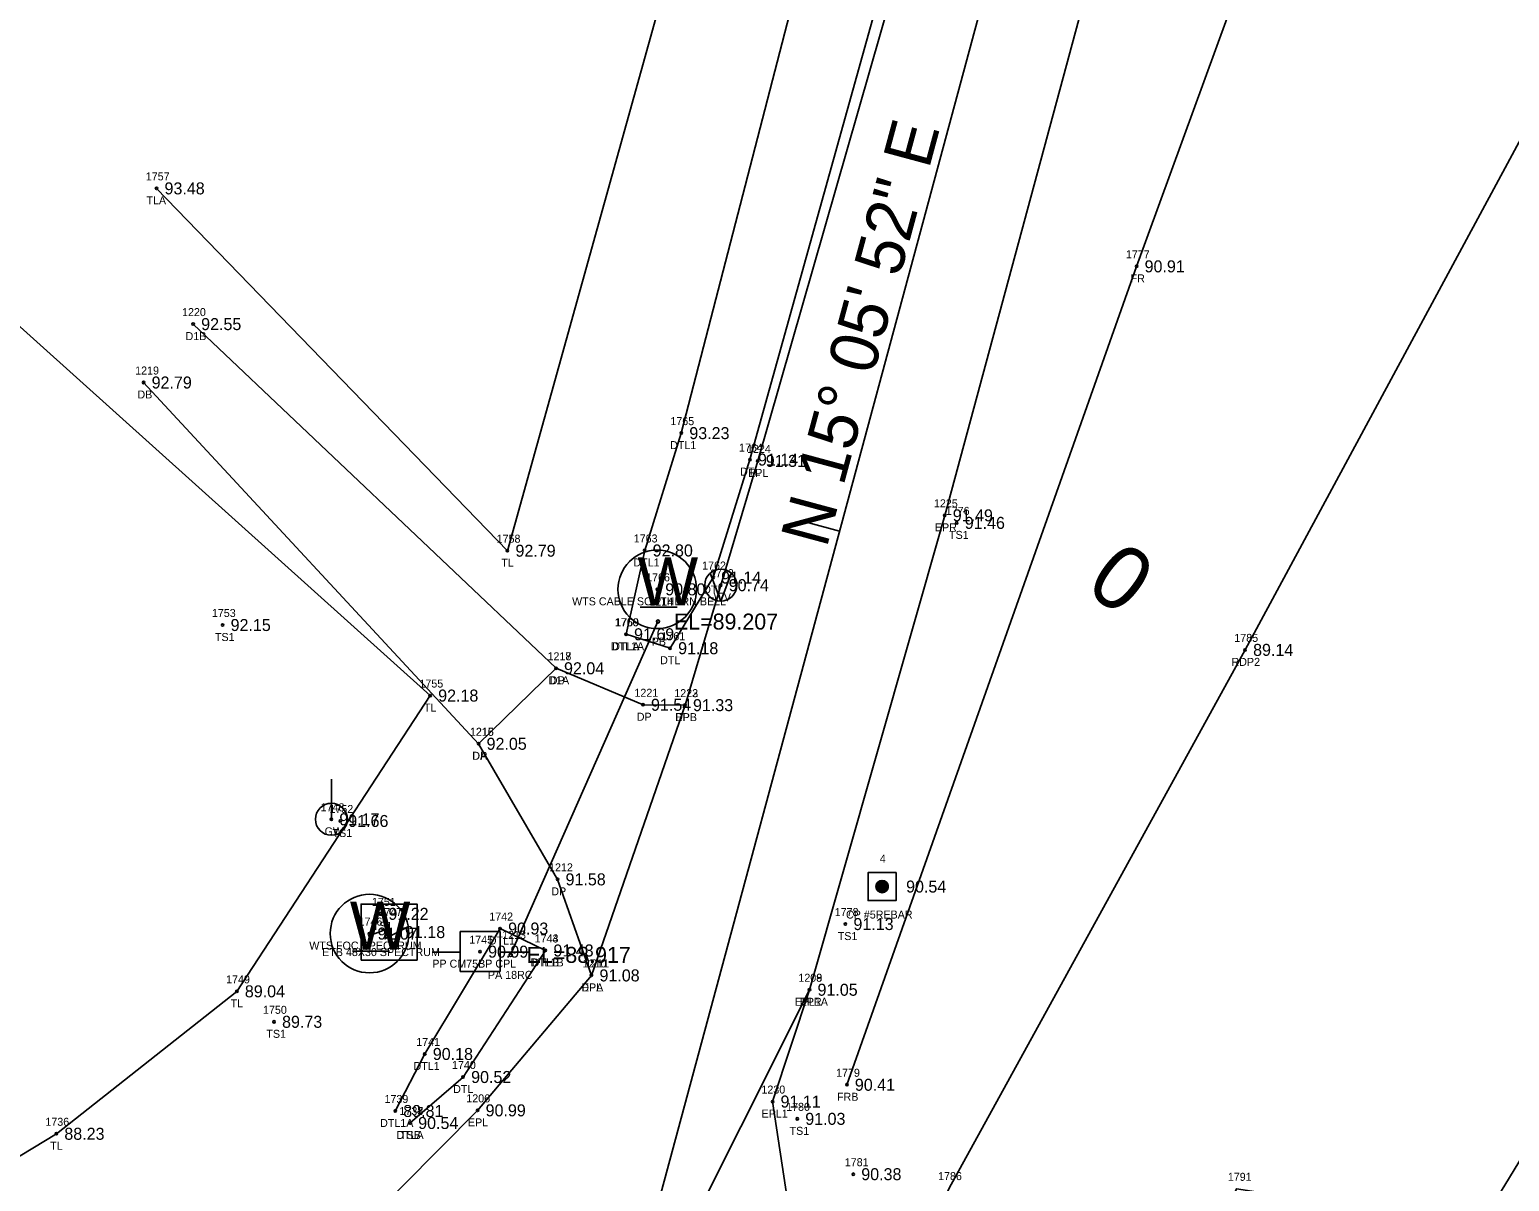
# Model space of a CAD drawing. Extents: x 2529517 to 2532038, y 935000 to 936944.
# Drawn here: x 2531691.2 to 2531876.1, y 936351.6 to 936495.6 of the extents above; entities that cross this region are included whole.
import ezdxf

# ---------------------------------------------------------------- set-up
doc = ezdxf.new("R2010")
doc.units = 0
for name, color, linetype in [('Default', 7, 'Continuous'), ('RD_DTM_BkLn_txCode', 7, 'Continuous'), ('RD_EX_DR_ErosCtrl', 7, 'Continuous'), ('RD_EX_DR_ErosCtrl_txCode', 7, 'Continuous'), ('RD_EX_DR_Pipe', 7, 'Continuous'), ('RD_EX_DR_Pipe_txCode', 7, 'Continuous'), ('RD_EX_Driveway', 7, 'Continuous'), ('RD_EX_Driveway_txCode', 7, 'Continuous'), ('RD_EX_Fence_Other', 7, 'Continuous'), ('RD_EX_Fence_Other_txCode', 7, 'Continuous'), ('RD_EX_H2O', 7, 'Continuous'), ('RD_EX_H2O_txCode', 7, 'Continuous'), ('RD_EX_Road', 7, 'Continuous'), ('RD_EX_Road_txCode', 7, 'Continuous'), ('RD_EX_TX_DR_ErosCtrl_ELEV', 7, 'Continuous'), ('RD_EX_TX_Driveway_ELEV', 7, 'Continuous'), ('RD_EX_TX_Fence_Other_ELEV', 7, 'Continuous'), ('RD_EX_TX_H2O_ELEV', 7, 'Continuous'), ('RD_EX_TX_Misc_ELEV', 7, 'Continuous'), ('RD_EX_TX_Road_ELEV', 7, 'Continuous'), ('RD_EX_TX_UT_ELEV', 7, 'Continuous'), ('RD_EX_TX_VEG_ELEV', 7, 'Continuous'), ('RD_EX_UT', 7, 'Continuous'), ('RD_EX_UT_txCode', 7, 'Continuous'), ('RD_EX_VEG', 7, 'Continuous'), ('RD_EX_VEG_txCode', 7, 'Continuous'), ('RD_HC_Cl', 7, 'Continuous'), ('RD_HC_Data', 7, 'Continuous'), ('RD_HC_Data_Tic', 7, 'Continuous'), ('RD_HC_Survey', 7, 'Continuous'), ('RD_HC_Survey_ELEV', 7, 'Continuous'), ('RD_HC_Survey_txCode', 7, 'Continuous'), ('RD_HC_TX_Sta50', 7, 'Continuous'), ('RD_SMD_Locator', 7, 'Continuous'), ('RD_TX_Pipe_ElevEX', 7, 'Continuous')]:
    doc.layers.add(name, color=color, linetype=linetype)

msp = doc.modelspace()

# ---------------------------------------------------------------- linework, layer by layer
at = {"layer": 'Default'}
msp.add_line((2531768.07, 936342.55), (2531830.33, 936573.34), dxfattribs=at)
at = {"layer": 'RD_EX_DR_ErosCtrl'}
for points in [[(2531913.23, 936552.65), (2531879.89, 936486.26), (2531843.11, 936418.02), (2531806.11, 936350.73), (2531797.19, 936330.95), (2531817.13, 936316.37), (2531822.13, 936313.28)], [(2531826.03, 936317.37), (2531842.02, 936350.64), (2531872.46, 936345.98), (2531906.05, 936401.13), (2531944.32, 936458.1), (2531968.34, 936447.83), (2531976.81, 936458.99), (2531957.81, 936476.14), (2531966.51, 936493.14)]]:
    msp.add_lwpolyline(points, dxfattribs=at)
at = {"layer": 'RD_EX_DR_Pipe'}
msp.add_line((2531751.32, 936379.89), (2531769.73, 936421.56), dxfattribs=at)
at = {"layer": 'RD_EX_Driveway'}
for p, q in [((2531756.99, 936415.72), (2531711.64, 936458.75)), ((2531747.31, 936406.28), (2531705.45, 936451.45))]:
    msp.add_line(p, q, dxfattribs=at)
msp.add_lwpolyline([(2531761.42, 936377.32), (2531757.18, 936389.33), (2531747.31, 936406.28), (2531756.99, 936415.72), (2531767.86, 936411.16), (2531773.11, 936411.11)], dxfattribs=at)
at = {"layer": 'RD_EX_Fence_Other'}
msp.add_lwpolyline([(2531868.07, 936571.73), (2531829.55, 936465.97), (2531793.34, 936363.65)], dxfattribs=at)
at = {"layer": 'RD_EX_H2O'}
for points in [[(2531765.74, 936419.97), (2531768.07, 936430.45), (2531772.65, 936445.12), (2531791.42, 936517.8), (2531810.23, 936589.19)], [(2531765.74, 936419.97), (2531771.25, 936418.23), (2531776.62, 936427.07), (2531781.23, 936441.81), (2531801.62, 936515.08), (2531818.73, 936586.25)], [(2531736.9, 936360.37), (2531740.59, 936367.5), (2531750, 936383.18), (2531755.67, 936380.44)], [(2531738.76, 936358.87), (2531745.38, 936364.62), (2531755.67, 936380.44)]]:
    msp.add_lwpolyline(points, dxfattribs=at)
at = {"layer": 'RD_EX_Road'}
for points in [[(2531169.65, 936000.77), (2531208.79, 936024.95), (2531292.04, 936074.02), (2531376.24, 936123.7), (2531460.37, 936174.49), (2531542.92, 936223.44), (2531626.67, 936270.85), (2531672.4, 936298.39), (2531714.28, 936327.21), (2531747.19, 936360.45), (2531761.42, 936377.32), (2531773.11, 936411.11), (2531782.2, 936441.65), (2531803.17, 936514.76), (2531820.28, 936585.8)], [(2531180.82, 935982), (2531220.82, 936004.21), (2531303.54, 936053.39), (2531388.75, 936103.71), (2531472.27, 936152.98), (2531554.79, 936201.9), (2531638.11, 936250.92), (2531683.19, 936278.28), (2531730.37, 936304.55), (2531771.5, 936341.26), (2531788.67, 936375.53), (2531805.57, 936434.84), (2531825.53, 936508.74), (2531844.13, 936579.65)], [(2531788.67, 936375.53), (2531784.05, 936361.55), (2531786.68, 936344.28), (2531790.66, 936334.1), (2531795.41, 936327.11), (2531801.08, 936320.84), (2531849.6, 936283.17), (2531876.01, 936264.22), (2531894.71, 936249.13), (2531930.69, 936221.59), (2532010.91, 936160.51)]]:
    msp.add_lwpolyline(points, dxfattribs=at)
at = {"layer": 'RD_EX_UT'}
for p, q in [((2531777.57, 936424.11), (2531776.26, 936427.6)), ((2531777.57, 936424.11), (2531778.89, 936427.56)), ((2531767.51, 936423.38), (2531772.14, 936423.38)), ((2531728.91, 936396.84), (2531728.91, 936401.84)), ((2531749.99, 936382.8), (2531744.99, 936382.8)), ((2531744.99, 936382.8), (2531744.99, 936377.8)), ((2531749.99, 936377.8), (2531749.99, 936382.8)), ((2531731.55, 936380.34), (2531736.18, 936380.34)), ((2531741.56, 936380.24), (2531745.03, 936380.24)), ((2531749.92, 936380.24), (2531753.56, 936380.24)), ((2531744.99, 936377.8), (2531749.99, 936377.8))]:
    msp.add_line(p, q, dxfattribs=at)
msp.add_lwpolyline([(2531732.62, 936379.24), (2531732.62, 936386.24), (2531739.62, 936386.24), (2531739.62, 936379.24)], close=True, dxfattribs=at)
msp.add_lwpolyline([(2531733.52, 936382.23), (2531735.94, 936383.14), (2531735.6, 936381.89), (2531738.64, 936383.48)], dxfattribs=at)
for centre, radius in [((2531769.64, 936425.59), 4.91), ((2531777.57, 936426.11), 2), ((2531728.91, 936396.84), 2), ((2531733.68, 936382.55), 4.91)]:
    msp.add_circle(centre, radius, dxfattribs=at)
at = {"layer": 'RD_EX_VEG'}
for points in [[(2531707.06, 936475.72), (2531750.92, 936430.42), (2531796.48, 936594.01)], [(2531179.62, 936140.26), (2531216.45, 936067.89), (2531694.54, 936357.52), (2531717.1, 936375.33), (2531741.26, 936412.31), (2531677.61, 936469.53)]]:
    msp.add_lwpolyline(points, dxfattribs=at)
at = {"layer": 'RD_HC_Cl'}
msp.add_line((2531768.07, 936342.55), (2531830.33, 936573.34), dxfattribs=at)
at = {"layer": 'RD_HC_Data_Tic'}
msp.add_line((2531792.43, 936432.85), (2531788.57, 936433.89), dxfattribs=at)
at = {"layer": 'RD_HC_Survey'}
for p, q in [((2531796.99, 936388.25), (2531796.99, 936388.61)), ((2531797.02, 936388.17), (2531797.02, 936388.69)), ((2531797.04, 936388.11), (2531797.04, 936388.76)), ((2531797.06, 936388.06), (2531797.06, 936388.8)), ((2531797.09, 936388.02), (2531797.09, 936388.85)), ((2531797.11, 936387.98), (2531797.11, 936388.88)), ((2531797.14, 936387.95), (2531797.14, 936388.92)), ((2531797.16, 936387.92), (2531797.16, 936388.94)), ((2531797.19, 936387.9), (2531797.19, 936388.97)), ((2531797.21, 936387.87), (2531797.21, 936389)), ((2531797.24, 936387.85), (2531797.24, 936389.02)), ((2531797.26, 936387.83), (2531797.26, 936389.04)), ((2531797.29, 936387.81), (2531797.29, 936389.06)), ((2531797.31, 936387.79), (2531797.31, 936389.07)), ((2531797.34, 936387.78), (2531797.34, 936389.09)), ((2531797.36, 936387.76), (2531797.36, 936389.1)), ((2531797.39, 936387.75), (2531797.39, 936389.12)), ((2531797.41, 936387.74), (2531797.41, 936389.13)), ((2531797.44, 936387.73), (2531797.44, 936389.14)), ((2531797.46, 936387.72), (2531797.46, 936389.15)), ((2531797.49, 936387.71), (2531797.49, 936389.16)), ((2531797.51, 936387.7), (2531797.51, 936389.17)), ((2531797.53, 936387.69), (2531797.53, 936389.18)), ((2531797.56, 936387.68), (2531797.56, 936389.18)), ((2531797.58, 936387.68), (2531797.58, 936389.19)), ((2531797.61, 936387.67), (2531797.61, 936389.19)), ((2531797.63, 936387.67), (2531797.63, 936389.2)), ((2531797.66, 936387.67), (2531797.66, 936389.2)), ((2531797.68, 936387.67), (2531797.68, 936389.2)), ((2531797.71, 936387.66), (2531797.71, 936389.2)), ((2531797.73, 936387.66), (2531797.73, 936389.2)), ((2531797.76, 936387.66), (2531797.76, 936389.2)), ((2531797.78, 936387.66), (2531797.78, 936389.2)), ((2531797.81, 936387.67), (2531797.81, 936389.2)), ((2531797.83, 936387.67), (2531797.83, 936389.2)), ((2531797.86, 936387.67), (2531797.86, 936389.19)), ((2531797.88, 936387.68), (2531797.88, 936389.19)), ((2531797.91, 936387.68), (2531797.91, 936389.18)), ((2531797.93, 936387.69), (2531797.93, 936389.18)), ((2531797.96, 936387.69), (2531797.96, 936389.17)), ((2531797.98, 936387.7), (2531797.98, 936389.16)), ((2531798.01, 936387.71), (2531798.01, 936389.16)), ((2531798.03, 936387.72), (2531798.03, 936389.15)), ((2531798.05, 936387.73), (2531798.05, 936389.13)), ((2531798.08, 936387.74), (2531798.08, 936389.12)), ((2531798.1, 936387.76), (2531798.1, 936389.11)), ((2531798.13, 936387.77), (2531798.13, 936389.1)), ((2531798.15, 936387.79), (2531798.15, 936389.08)), ((2531798.18, 936387.8), (2531798.18, 936389.06)), ((2531798.2, 936387.82), (2531798.2, 936389.05)), ((2531798.23, 936387.84), (2531798.23, 936389.03)), ((2531798.25, 936387.86), (2531798.25, 936389.01)), ((2531798.28, 936387.88), (2531798.28, 936388.98)), ((2531798.3, 936387.91), (2531798.3, 936388.96)), ((2531798.33, 936387.94), (2531798.33, 936388.93)), ((2531798.35, 936387.97), (2531798.35, 936388.9)), ((2531798.38, 936388), (2531798.38, 936388.86)), ((2531798.4, 936388.04), (2531798.4, 936388.82)), ((2531798.43, 936388.09), (2531798.43, 936388.78)), ((2531798.45, 936388.14), (2531798.45, 936388.73)), ((2531798.48, 936388.21), (2531798.48, 936388.66)), ((2531798.5, 936388.32), (2531798.5, 936388.54))]:
    msp.add_line(p, q, dxfattribs=at)
msp.add_lwpolyline([(2531799.49, 936390.18), (2531795.99, 936390.18), (2531795.99, 936386.68), (2531799.49, 936386.68)], close=True, dxfattribs=at)
msp.add_circle((2531797.74, 936388.43), 0.769, dxfattribs=at)
at = {"layer": 'RD_SMD_Locator'}
for centre, radius in [((2531707.06, 936475.72), 0.15), ((2531829.55, 936465.97), 0.15), ((2531711.64, 936458.75), 0.15), ((2531705.45, 936451.45), 0.15), ((2531772.65, 936445.12), 0.15), ((2531781.23, 936441.81), 0.15), ((2531782.2, 936441.65), 0.15), ((2531805.57, 936434.84), 0.15), ((2531807.07, 936433.9), 0.15), ((2531750.92, 936430.42), 0.15), ((2531768.07, 936430.45), 0.15), ((2531769.64, 936425.59), 0.15), ((2531776.62, 936427.07), 0.15), ((2531777.57, 936426.11), 0.15), ((2531715.32, 936421.13), 0.15), ((2531765.74, 936419.97), 0.15), ((2531765.74, 936419.97), 0.15), ((2531769.73, 936421.56), 0.2), ((2531771.25, 936418.23), 0.15), ((2531843.11, 936418.02), 0.15), ((2531756.99, 936415.72), 0.15), ((2531756.99, 936415.72), 0.15), ((2531741.26, 936412.31), 0.15), ((2531767.86, 936411.16), 0.15), ((2531773.11, 936411.11), 0.15), ((2531773.11, 936411.11), 0.15), ((2531747.31, 936406.28), 0.15), ((2531747.31, 936406.28), 0.15), ((2531728.91, 936396.84), 0.15), ((2531730.02, 936396.63), 0.15), ((2531757.18, 936389.33), 0.15), ((2531797.74, 936388.43), 0.15), ((2531735.04, 936385.02), 0.15), ((2531750, 936383.18), 0.15), ((2531793.16, 936383.74), 0.15), ((2531733.68, 936382.55), 0.15), ((2531736.12, 936382.74), 0.15), ((2531747.5, 936380.29), 0.15), ((2531751.32, 936379.89), 0.2), ((2531755.67, 936380.44), 0.15), ((2531755.67, 936380.44), 0.15), ((2531761.42, 936377.32), 0.15), ((2531761.42, 936377.32), 0.15), ((2531788.67, 936375.53), 0.15), ((2531788.67, 936375.53), 0.15), ((2531717.1, 936375.33), 0.15), ((2531721.75, 936371.52), 0.15), ((2531740.59, 936367.5), 0.15), ((2531745.38, 936364.62), 0.15), ((2531793.34, 936363.65), 0.15), ((2531784.05, 936361.55), 0.15), ((2531736.9, 936360.37), 0.15), ((2531738.76, 936358.87), 0.15), ((2531738.76, 936358.87), 0.15), ((2531747.19, 936360.45), 0.15), ((2531787.14, 936359.39), 0.15), ((2531694.54, 936357.52), 0.15), ((2531794.14, 936352.47), 0.15)]:
    msp.add_circle(centre, radius, dxfattribs=at)

# ---------------------------------------------------------------- texts
at = {"layer": 'RD_DTM_BkLn_txCode'}
for s, p in [('1776', (2531805.7, 936434.9)), ('TS1', (2531806.11, 936431.9)), ('1753', (2531713.98, 936422.13)), ('TS1', (2531714.36, 936419.13)), ('1752', (2531728.67, 936397.63)), ('TS1', (2531729.06, 936394.63)), ('1751', (2531733.98, 936386.02)), ('1778', (2531791.82, 936384.74)), ('TS1', (2531734.08, 936383.02)), ('TS1', (2531792.2, 936381.74)), ('1750', (2531720.37, 936372.52)), ('TS1', (2531720.79, 936369.52)), ('1737', (2531737.42, 936359.87)), ('1780', (2531785.75, 936360.39)), ('TSB', (2531737.49, 936356.87)), ('TS1', (2531786.18, 936357.39)), ('1781', (2531793.08, 936353.47))]:
    msp.add_text(s, height=1, dxfattribs=at).set_placement(p)
at = {"layer": 'RD_EX_DR_ErosCtrl_txCode'}
for s, p in [('1785', (2531841.76, 936419.02)), ('RDP2', (2531841.41, 936416.02)), ('1786', (2531804.74, 936351.73)), ('1791', (2531840.95, 936351.64))]:
    msp.add_text(s, height=1, dxfattribs=at).set_placement(p)
at = {"layer": 'RD_EX_DR_Pipe_txCode'}
for s, p in [('1214', (2531768.66, 936423.56)), ('PB', (2531768.95, 936418.56)), ('1213', (2531750.26, 936381.89)), ('PA 18RC', (2531748.48, 936376.89))]:
    msp.add_text(s, height=1, dxfattribs=at).set_placement(p)
at = {"layer": 'RD_EX_Driveway_txCode'}
for s, p in [('1220', (2531710.25, 936459.75)), ('D1B', (2531710.69, 936456.75)), ('1219', (2531704.39, 936452.45)), ('DB', (2531704.67, 936449.45)), ('1217', (2531755.93, 936416.72)), ('1218', (2531755.93, 936416.72)), ('D1A', (2531756.03, 936413.72)), ('DP', (2531756.21, 936413.72)), ('1221', (2531766.79, 936412.16)), ('1222', (2531771.77, 936412.11)), ('DP', (2531767.08, 936409.16)), ('DPB', (2531771.86, 936409.11)), ('1216', (2531746.22, 936407.28)), ('1215', (2531746.24, 936407.28)), ('DA', (2531746.51, 936404.28)), ('DP', (2531746.53, 936404.28)), ('1212', (2531756.12, 936390.33)), ('DP', (2531756.4, 936387.33)), ('1211', (2531760.64, 936378.32)), ('DPA', (2531760.15, 936375.32))]:
    msp.add_text(s, height=1, dxfattribs=at).set_placement(p)
at = {"layer": 'RD_EX_Fence_Other_txCode'}
for s, p in [('1777', (2531828.21, 936466.97)), ('FR', (2531828.8, 936463.97)), ('1779', (2531791.99, 936364.65)), ('FRB', (2531792.11, 936361.65))]:
    msp.add_text(s, height=1, dxfattribs=at).set_placement(p)
at = {"layer": 'RD_EX_H2O_txCode'}
for s, p in [('1765', (2531771.28, 936446.12)), ('DTL1', (2531771.24, 936443.12)), ('1764', (2531779.86, 936442.81)), ('DTL', (2531779.99, 936439.81)), ('1763', (2531766.7, 936431.45)), ('DTL1', (2531766.66, 936428.45)), ('1762', (2531775.25, 936428.07)), ('DTL', (2531775.38, 936425.07)), ('1760', (2531764.33, 936420.97)), ('1759', (2531764.39, 936420.97)), ('1761', (2531770.16, 936419.23)), ('DTL1A', (2531763.84, 936417.97)), ('DTLA', (2531764.01, 936417.97)), ('DTL', (2531770, 936416.23)), ('1742', (2531748.65, 936384.18)), ('DTL1', (2531748.59, 936381.18)), ('1743', (2531754.32, 936381.44)), ('1744', (2531754.32, 936381.44)), ('DTL1B', (2531753.78, 936378.44)), ('DTLB', (2531753.95, 936378.44)), ('1741', (2531739.52, 936368.5)), ('DTL1', (2531739.18, 936365.5)), ('1740', (2531743.99, 936365.62)), ('DTL', (2531744.13, 936362.62)), ('1739', (2531735.55, 936361.37)), ('1738', (2531737.42, 936359.87)), ('DTL1A', (2531735, 936358.37)), ('DTLA', (2531737.03, 936356.87))]:
    msp.add_text(s, height=1, dxfattribs=at).set_placement(p)
at = {"layer": 'RD_EX_Road_txCode'}
for s, p in [('1224', (2531780.86, 936442.65)), ('EPL', (2531781, 936439.65)), ('1225', (2531804.22, 936435.84)), ('EPR', (2531804.34, 936432.84)), ('1223', (2531771.77, 936412.11)), ('EPL', (2531771.91, 936409.11)), ('1210', (2531760.32, 936378.32)), ('1208', (2531787.28, 936376.53)), ('1209', (2531787.28, 936376.53)), ('EPL', (2531760.22, 936375.32)), ('EPL1A', (2531786.81, 936373.53)), ('EPR', (2531787.44, 936373.53)), ('1230', (2531782.66, 936362.55)), ('1206', (2531745.78, 936361.45)), ('EPL', (2531745.98, 936358.45)), ('EPL1', (2531782.68, 936359.55))]:
    msp.add_text(s, height=1, dxfattribs=at).set_placement(p)
at = {"layer": 'RD_EX_TX_DR_ErosCtrl_ELEV'}
msp.add_text('89.14', height=1.5, dxfattribs=at).set_placement((2531844.11, 936417.27))
at = {"layer": 'RD_EX_TX_Driveway_ELEV'}
for s, p in [('92.55', (2531712.64, 936458)), ('92.79', (2531706.45, 936450.7)), ('92.04', (2531757.99, 936414.97)), ('92.04', (2531757.99, 936414.97)), ('91.54', (2531768.86, 936410.41)), ('91.33', (2531774.11, 936410.36)), ('92.05', (2531748.31, 936405.53)), ('92.05', (2531748.31, 936405.53)), ('91.58', (2531758.18, 936388.58)), ('91.08', (2531762.42, 936376.57))]:
    msp.add_text(s, height=1.5, dxfattribs=at).set_placement(p)
at = {"layer": 'RD_EX_TX_Fence_Other_ELEV'}
for s, p in [('90.91', (2531830.55, 936465.22)), ('90.41', (2531794.34, 936362.9))]:
    msp.add_text(s, height=1.5, dxfattribs=at).set_placement(p)
at = {"layer": 'RD_EX_TX_H2O_ELEV'}
for s, p in [('93.23', (2531773.65, 936444.37)), ('91.14', (2531782.23, 936441.06)), ('92.80', (2531769.07, 936429.7)), ('91.14', (2531777.62, 936426.32)), ('91.69', (2531766.74, 936419.22)), ('91.69', (2531766.74, 936419.22)), ('91.18', (2531772.25, 936417.48)), ('90.93', (2531751, 936382.43)), ('91.43', (2531756.67, 936379.69)), ('91.43', (2531756.67, 936379.69)), ('90.18', (2531741.59, 936366.75)), ('90.52', (2531746.38, 936363.87)), ('89.81', (2531737.9, 936359.62)), ('90.54', (2531739.76, 936358.12))]:
    msp.add_text(s, height=1.5, dxfattribs=at).set_placement(p)
at = {"layer": 'RD_EX_TX_Misc_ELEV'}
for s, p in [('91.46', (2531808.07, 936433.15)), ('92.15', (2531716.32, 936420.38)), ('91.66', (2531731.02, 936395.88)), ('91.22', (2531736.04, 936384.27)), ('91.13', (2531794.16, 936382.99)), ('89.73', (2531722.75, 936370.77)), ('90.54', (2531739.76, 936358.12)), ('91.03', (2531788.14, 936358.64)), ('90.38', (2531795.14, 936351.72))]:
    msp.add_text(s, height=1.5, dxfattribs=at).set_placement(p)
at = {"layer": 'RD_EX_TX_Road_ELEV'}
for s, p in [('91.31', (2531783.2, 936440.9)), ('91.49', (2531806.57, 936434.09)), ('91.33', (2531774.11, 936410.36)), ('91.08', (2531762.42, 936376.57)), ('91.05', (2531789.67, 936374.78)), ('91.05', (2531789.67, 936374.78)), ('90.99', (2531748.19, 936359.7)), ('91.11', (2531785.05, 936360.8))]:
    msp.add_text(s, height=1.5, dxfattribs=at).set_placement(p)
at = {"layer": 'RD_EX_TX_UT_ELEV'}
for s, p in [('90.80', (2531770.64, 936424.84)), ('90.74', (2531778.57, 936425.36)), ('91.17', (2531729.91, 936396.09)), ('91.07', (2531734.68, 936381.8)), ('91.18', (2531738.12, 936381.99))]:
    msp.add_text(s, height=1.5, dxfattribs=at).set_placement(p)
at = {"layer": 'RD_EX_TX_VEG_ELEV'}
for s, p in [('93.48', (2531708.06, 936474.97)), ('92.79', (2531751.92, 936429.67)), ('92.18', (2531742.26, 936411.56)), ('89.04', (2531718.1, 936374.58)), ('88.23', (2531695.54, 936356.77))]:
    msp.add_text(s, height=1.5, dxfattribs=at).set_placement(p)
at = {"layer": 'RD_EX_UT'}
for p in [(2531767.18, 936423.59), (2531731.22, 936380.54)]:
    msp.add_text('W', height=6, dxfattribs=at).set_placement(p)
at = {"layer": 'RD_EX_UT_txCode'}
for s, p in [('1766', (2531768.25, 936426.59)), ('1772', (2531776.22, 936427.11)), ('WTS CABLE SOUTHERN BELL', (2531759, 936423.59)), ('WV', (2531776.71, 936424.11)), ('1748', (2531727.57, 936397.84)), ('GW', (2531728.07, 936394.84)), ('1747', (2531734.78, 936384.74)), ('1746', (2531732.31, 936383.55)), ('WTS FOC SPECTRUM', (2531726.15, 936380.55)), ('1745', (2531746.15, 936381.29)), ('ETB 48X30 SPECTRUM', (2531727.76, 936379.74)), ('PP CM75BP CPL', (2531741.53, 936378.29))]:
    msp.add_text(s, height=1, dxfattribs=at).set_placement(p)
at = {"layer": 'RD_EX_VEG_txCode'}
for s, p in [('1757', (2531705.72, 936476.72)), ('TLA', (2531705.8, 936473.72)), ('1758', (2531749.57, 936431.42)), ('TL', (2531750.15, 936428.42)), ('1755', (2531739.92, 936413.31)), ('TL', (2531740.49, 936410.31)), ('1749', (2531715.76, 936376.33)), ('TL', (2531716.33, 936373.33)), ('1736', (2531693.17, 936358.52)), ('TL', (2531693.77, 936355.52))]:
    msp.add_text(s, height=1, dxfattribs=at).set_placement(p)
at = {"layer": 'RD_HC_Data'}
msp.add_text('N 15%%d 05\' 52" E', height=6, rotation=74.9022, dxfattribs=at).set_placement((2531790.8, 936430.64))
at = {"layer": 'RD_HC_Survey_ELEV'}
for s, p in [('90.54', (2531800.74, 936387.68)), ('90.99', (2531748.5, 936379.54))]:
    msp.add_text(s, height=1.5, dxfattribs=at).set_placement(p)
at = {"layer": 'RD_HC_Survey_txCode'}
for s, p in [('4', (2531797.46, 936391.43)), ('CP #5REBAR', (2531793.23, 936384.43))]:
    msp.add_text(s, height=1, dxfattribs=at).set_placement(p)
at = {"layer": 'RD_HC_TX_Sta50'}
msp.add_text('0', height=8, rotation=322.8882, dxfattribs=at).set_placement((2531822.88, 936425.62))
at = {"layer": 'RD_TX_Pipe_ElevEX'}
for s, p in [('EL=89.207', (2531771.73, 936420.56)), ('EL=88.917', (2531753.32, 936378.89))]:
    msp.add_text(s, height=2, dxfattribs=at).set_placement(p)

doc.saveas('drawing.dxf')
